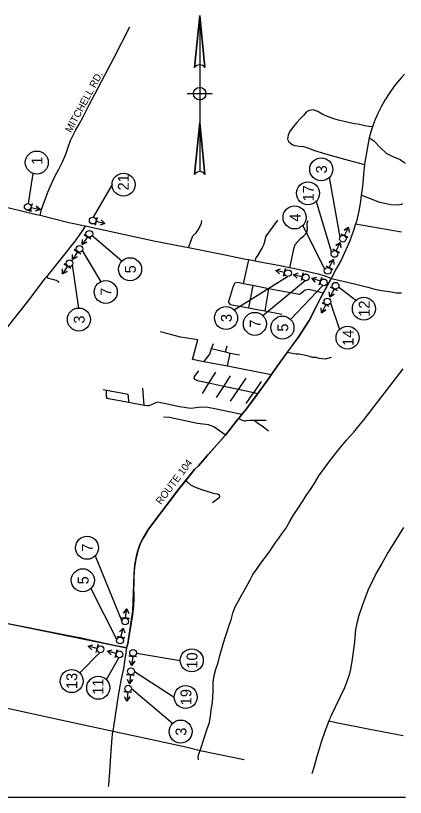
# Model space of a CAD drawing. Extents: x 1123038 to 1172987, y 554419 to 623636.
# Drawn here: x 1134979 to 1140976, y 566570 to 578600 of the extents above; entities that cross this region are included whole.
import ezdxf

# ---------------------------------------------------------------- set-up
doc = ezdxf.new("R2010")
doc.units = 0
for name, color, linetype in [('ANNOTATION', 7, 'Continuous'), ('CENTERLINE', 7, 'Continuous'), ('D_Text_Standard', 7, 'Continuous'), ('Default', 7, 'Continuous'), ('H_V CONTROLS', 7, 'Continuous'), ('Maine_E911_Roads', 7, 'Continuous'), ('Metwp24L', 7, 'Continuous')]:
    doc.layers.add(name, color=color, linetype=linetype)

msp = doc.modelspace()

# ---------------------------------------------------------------- linework, layer by layer
at = {"layer": 'ANNOTATION'}
msp.add_line((1140976, 566570), (1123076, 566570), dxfattribs=at)
at = {"layer": 'CENTERLINE'}
for points in [[(1138845, 572976), (1139007, 573210), (1139242, 573535), (1139325, 573649), (1139494, 573909), (1139710, 574328), (1139836, 574557)], [(1136846, 570308), (1136859, 570363), (1136896, 570470), (1136941, 570559), (1137024, 570699), (1137481, 571305), (1137732, 571618), (1137792, 571673), (1137941, 571847), (1138206, 572143), (1138405, 572396), (1138421, 572409), (1138548, 572572), (1138845, 572976)], [(1130112, 570269), (1130133, 570251), (1130186, 570222), (1130224, 570205), (1130658, 570099), (1130944, 570047), (1136685, 568871)], [(1136685, 568871), (1136707, 568934), (1136784, 569437), (1136801, 570001), (1136813, 570149), (1136846, 570308)]]:
    msp.add_lwpolyline(points, dxfattribs=at)
at = {"layer": 'D_Text_Standard'}
for p, q in [((1135243, 576172), (1135174, 575709)), ((1136463, 576000), (1136174, 575497)), ((1139806, 576110), (1139966, 575190)), ((1139602, 575741), (1139837, 574956)), ((1139396, 575370), (1139733, 574697)), ((1136615, 574823), (1136157, 575214)), ((1136005, 574984), (1136290, 574502)), ((1135952, 574101), (1135852, 574763)), ((1138342, 574073), (1139161, 574586)), ((1139434, 574521), (1138785, 573982)), ((1139210, 573925), (1139705, 574446)), ((1140212, 574215), (1139949, 574421)), ((1139823, 574179), (1139961, 573769)), ((1136203, 570286), (1136612, 569282)), ((1136138, 569787), (1136535, 568996)), ((1135966, 568485), (1136274, 568798)), ((1136838, 568789), (1137512, 568679)), ((1136375, 568382), (1136568, 568720)), ((1137512, 568679), (1137512, 568679)), ((1136806, 568506), (1137418, 568114)), ((1137393, 567708), (1136762, 568240))]:
    msp.add_line(p, q, dxfattribs=at)
for centre in [(1135305, 576340), (1139681, 576235), (1136639, 576000), (1139477, 575866), (1139271, 575495), (1136740, 574698), (1136366, 574348), (1140337, 574090), (1135952, 573924), (1138217, 573948), (1138660, 573857), (1139085, 573800), (1140086, 573644), (1136078, 570411), (1136013, 569912), (1137689, 568679), (1135841, 568360), (1136250, 568257), (1137595, 568114), (1137518, 567583)]:
    msp.add_circle(centre, 177, dxfattribs=at)
at = {"layer": 'Default'}
for points in [[(1135231, 575707), (1135204, 575587), (1135218, 575647), (1135354, 575616), (1135295, 575670), (1135354, 575616), (1135282, 575590)], [(1136232, 575494), (1136205, 575375), (1136218, 575435), (1136354, 575404), (1136295, 575458), (1136354, 575404), (1136282, 575377)], [(1139984, 575245), (1140091, 575188), (1140038, 575217), (1140103, 575340), (1140036, 575297), (1140103, 575340), (1140110, 575263)], [(1136134, 575162), (1136033, 575230), (1136083, 575196), (1136005, 575080), (1136077, 575116), (1136005, 575080), (1136007, 575157)], [(1139855, 575010), (1139963, 574953), (1139909, 574982), (1139974, 575105), (1139907, 575062), (1139974, 575105), (1139981, 575028)], [(1135982, 574932), (1135881, 575000), (1135931, 574966), (1135853, 574850), (1135925, 574886), (1135853, 574850), (1135855, 574927)], [(1139750, 574751), (1139858, 574694), (1139804, 574723), (1139870, 574846), (1139802, 574803), (1139870, 574846), (1139876, 574769)], [(1135829, 574710), (1135728, 574779), (1135779, 574745), (1135700, 574629), (1135772, 574665), (1135700, 574629), (1135702, 574706)], [(1139103, 574589), (1139130, 574708), (1139117, 574648), (1138981, 574679), (1139040, 574625), (1138981, 574679), (1139053, 574706)], [(1139377, 574523), (1139404, 574643), (1139390, 574583), (1139254, 574614), (1139313, 574560), (1139254, 574614), (1139326, 574641)], [(1139648, 574456), (1139690, 574570), (1139669, 574513), (1139538, 574561), (1139590, 574500), (1139538, 574561), (1139613, 574578)], [(1139932, 574367), (1139824, 574424), (1139878, 574395), (1139812, 574272), (1139880, 574315), (1139812, 574272), (1139806, 574349)], [(1139806, 574124), (1139698, 574181), (1139752, 574152), (1139686, 574029), (1139754, 574072), (1139686, 574029), (1139679, 574106)], [(1136610, 569340), (1136731, 569323), (1136670, 569331), (1136689, 569470), (1136641, 569406), (1136689, 569470), (1136722, 569400)], [(1136539, 569053), (1136657, 569023), (1136598, 569038), (1136632, 569174), (1136577, 569116), (1136632, 569174), (1136657, 569101)], [(1136217, 568802), (1136247, 568921), (1136232, 568861), (1136096, 568896), (1136154, 568840), (1136096, 568896), (1136169, 568920)], [(1136510, 568724), (1136540, 568842), (1136525, 568783), (1136390, 568818), (1136448, 568762), (1136390, 568818), (1136463, 568842)], [(1136841, 568732), (1136720, 568746), (1136780, 568739), (1136764, 568600), (1136811, 568665), (1136764, 568600), (1136730, 568670)], [(1136809, 568448), (1136687, 568463), (1136748, 568456), (1136731, 568317), (1136779, 568382), (1136731, 568317), (1136698, 568386)], [(1136765, 568182), (1136644, 568197), (1136705, 568189), (1136688, 568051), (1136735, 568115), (1136688, 568051), (1136654, 568120)]]:
    msp.add_lwpolyline(points, dxfattribs=at)
for centre in [(1135165, 575658), (1136165, 575446), (1136113, 575241), (1140013, 575168), (1135961, 575011), (1139884, 574933), (1135808, 574790), (1139170, 574637), (1139780, 574674), (1139443, 574572), (1139720, 574495), (1139902, 574444), (1139776, 574201), (1136664, 569278), (1136585, 568986), (1136284, 568849), (1136578, 568771), (1136786, 568793), (1136754, 568510), (1136710, 568243)]:
    msp.add_circle(centre, 51.9, dxfattribs=at)
at = {"layer": 'H_V CONTROLS'}
for p, q in [((1137732, 577800), (1137812, 578600)), ((1137812, 578600), (1137812, 576200)), ((1137812, 578600), (1137892, 577800)), ((1137620, 577400), (1138004, 577400)), ((1137732, 576157), (1137812, 576957)), ((1137812, 576957), (1137892, 576157))]:
    msp.add_line(p, q, dxfattribs=at)
for points in [[(1137892, 577800), (1137812, 578600), (1137772, 578200), (1137732, 577800)], [(1137892, 576157), (1137812, 576957), (1137772, 576557), (1137732, 576157)]]:
    msp.add_lwpolyline(points, dxfattribs=at)
msp.add_circle((1137812, 577400), 96, dxfattribs=at)
for centre in [(1137812, 577747), (1137812, 577747), (1137812, 576104), (1137812, 576104)]:
    msp.add_arc(centre, 96, 33.5573, 146.4427, dxfattribs=at)
at = {"layer": 'Maine_E911_Roads'}
for points in [[(1135357, 575524), (1135379, 575618), (1135474, 575882), (1135531, 576011), (1135583, 576127), (1135642, 576239), (1135706, 576359), (1135750, 576468), (1135786, 576577), (1135822, 576681), (1135901, 576831), (1135954, 576929), (1136011, 577033), (1136105, 577215), (1136255, 577502), (1136496, 577957), (1136736, 578426)], [(1140961, 577699), (1140909, 577641), (1140806, 577514), (1140725, 577403), (1140661, 577302), (1140604, 577196), (1140560, 577105), (1140512, 577002), (1140482, 576918), (1140468, 576887)], [(1140468, 576887), (1140416, 576892), (1140353, 576903), (1140269, 576924), (1140192, 576936), (1140121, 576953), (1140057, 576968), (1139946, 576991), (1139874, 577011), (1139778, 577047), (1139697, 577085), (1139627, 577125), (1139555, 577150), (1139497, 577141), (1139447, 577116), (1139407, 577061), (1139358, 577011), (1139302, 576951), (1139233, 576868), (1139194, 576810), (1139172, 576762), (1139160, 576701), (1139182, 576660), (1139209, 576637), (1139244, 576613), (1139273, 576601), (1139342, 576594), (1139410, 576587), (1139476, 576566), (1139562, 576532), (1139745, 576476), (1140037, 576390), (1140348, 576307)], [(1140468, 576887), (1140445, 576813), (1140420, 576722)], [(1140420, 576722), (1140359, 576376), (1140348, 576307)], [(1140420, 576722), (1140485, 576679), (1140592, 576566), (1140679, 576482), (1140783, 576432), (1140894, 576387), (1140952, 576347), (1140971, 576327)], [(1135357, 575524), (1135278, 575539), (1134683, 575685), (1133226, 575982), (1132575, 576122), (1132376, 576166), (1131980, 576258), (1131516, 576373), (1131252, 576438)], [(1140348, 576307), (1140334, 576164), (1140319, 576019), (1140304, 575898), (1140297, 575842), (1140297, 575837)], [(1140297, 575837), (1140286, 575746), (1140266, 575618), (1140222, 575432), (1140211, 575397)], [(1140930, 575706), (1140917, 575693), (1140886, 575687), (1140843, 575685), (1140754, 575690), (1140585, 575727), (1140297, 575837)], [(1135230, 575587), (1135151, 575606)], [(1136048, 575360), (1135796, 575411), (1135357, 575524)], [(1137637, 575025), (1137648, 575057), (1137706, 575212), (1137758, 575259), (1137792, 575309), (1137838, 575406), (1137843, 575447)], [(1138663, 574823), (1138674, 574861), (1138714, 574927), (1138775, 575023), (1138798, 575075), (1138820, 575144), (1138831, 575197), (1138848, 575228), (1139012, 575454)], [(1139200, 574719), (1139238, 574911), (1139259, 575013), (1139282, 575078), (1139360, 575173), (1139408, 575206), (1139462, 575261), (1139471, 575311), (1139463, 575375), (1139464, 575409), (1139478, 575447)], [(1140211, 575397), (1140175, 575278), (1140120, 575135), (1140060, 574997), (1139986, 574839), (1139903, 574686), (1139854, 574590), (1139836, 574557)], [(1140211, 575397), (1140914, 575273)], [(1136048, 575360), (1135993, 575272), (1135896, 575134), (1135452, 574583)], [(1137637, 575025), (1137555, 575042), (1137107, 575130), (1136048, 575360)], [(1138561, 574842), (1138521, 574850), (1138151, 574923), (1137637, 575025)], [(1138561, 574842), (1138480, 574475)], [(1138663, 574823), (1138643, 574826), (1138561, 574842)], [(1139200, 574719), (1139052, 574749), (1138742, 574809), (1138663, 574823)], [(1139836, 574557), (1139727, 574596), (1139653, 574615), (1139320, 574694), (1139200, 574719)], [(1135452, 574583), (1135423, 574548), (1135180, 574229), (1134927, 573903), (1134650, 573556), (1134620, 573517), (1134244, 573043), (1134002, 572749), (1133422, 572023), (1132636, 571025), (1131932, 570140), (1131751, 569881)], [(1135452, 574583), (1135487, 574559), (1135521, 574548), (1135568, 574538), (1135579, 574535), (1135602, 574527), (1135610, 574524), (1135624, 574517), (1135634, 574511), (1135645, 574496)], [(1139836, 574557), (1139710, 574328)], [(1139836, 574557), (1139999, 574519), (1140213, 574468), (1140400, 574422), (1140505, 574393), (1140611, 574370), (1140648, 574367), (1140727, 574354), (1140841, 574333), (1140917, 574337)], [(1138480, 574475), (1138396, 574492), (1138354, 574484), (1138325, 574435), (1138266, 574233), (1138255, 574199), (1138252, 574184), (1138280, 574157), (1138560, 574106)], [(1138628, 574446), (1138480, 574475)], [(1138628, 574446), (1138560, 574106)], [(1138872, 574396), (1138628, 574446)], [(1138872, 574396), (1138812, 574059)], [(1139710, 574328), (1139493, 574384), (1139434, 574378), (1139364, 574321), (1139345, 574309), (1138872, 574396)], [(1139710, 574328), (1139669, 574254), (1139494, 573909), (1139325, 573649), (1139159, 573421)], [(1138560, 574106), (1138812, 574059)], [(1138812, 574059), (1139074, 574007)], [(1137782, 573610), (1137518, 573650), (1137206, 573736)], [(1137877, 573273), (1137702, 573311), (1137782, 573610)], [(1137877, 573273), (1137965, 573393), (1137995, 573476)], [(1137995, 573476), (1138023, 573555)], [(1137995, 573476), (1138209, 573425)], [(1138209, 573425), (1138232, 573521)], [(1138209, 573425), (1138275, 573408), (1138280, 573408)], [(1138237, 573204), (1138280, 573408)], [(1138280, 573408), (1138426, 573379)], [(1139159, 573421), (1139153, 573413), (1139007, 573210), (1138911, 573071)], [(1139159, 573421), (1139209, 573409), (1139294, 573396), (1139335, 573395), (1139418, 573383), (1139482, 573364), (1139541, 573347), (1139596, 573342), (1139645, 573329), (1139747, 573321), (1139840, 573346)], [(1138237, 573204), (1137877, 573273)], [(1137951, 572943), (1137778, 572980), (1137742, 573002), (1137727, 573021), (1137731, 573048), (1137799, 573134)], [(1137951, 572943), (1138060, 573114)], [(1138911, 573071), (1138237, 573204)], [(1138185, 572893), (1138284, 573059)], [(1138409, 572847), (1138528, 573020)], [(1138911, 573071), (1138885, 573034), (1138805, 572918), (1138720, 572805), (1138701, 572780)], [(1136956, 572601), (1136937, 572865)], [(1137852, 572785), (1137951, 572943)], [(1138185, 572893), (1137951, 572943)], [(1138070, 572722), (1138185, 572893)], [(1138409, 572847), (1138185, 572893)], [(1138643, 572797), (1138763, 572972)], [(1136377, 572831), (1136325, 572842)], [(1136720, 572645), (1136714, 572753), (1136703, 572771), (1136684, 572774), (1136377, 572831)], [(1136720, 572645), (1136409, 572702), (1136391, 572708), (1136377, 572733), (1136377, 572831)], [(1138287, 572668), (1138409, 572847)], [(1138643, 572797), (1138409, 572847)], [(1138701, 572780), (1138693, 572768), (1138548, 572572), (1138462, 572463)], [(1138526, 572634), (1138627, 572780), (1138643, 572797)], [(1138701, 572780), (1138643, 572797)], [(1136956, 572601), (1136720, 572645)], [(1138462, 572463), (1138043, 572547), (1137939, 572570), (1137836, 572577), (1137675, 572553), (1137499, 572579), (1137265, 572631), (1137180, 572649), (1137160, 572651), (1137134, 572644), (1137030, 572598), (1137002, 572596), (1136956, 572601)], [(1138206, 572143), (1138081, 572238), (1138030, 572273), (1137949, 572303), (1137779, 572325), (1137348, 572414), (1137254, 572423)], [(1138413, 572403), (1138405, 572396), (1138206, 572143)], [(1138462, 572463), (1138421, 572409), (1138413, 572403)], [(1138413, 572403), (1138463, 572374), (1138478, 572369), (1138493, 572366), (1138509, 572367), (1138524, 572368), (1138584, 572373), (1138617, 572375), (1138648, 572374)], [(1138648, 572374), (1138836, 572375)], [(1138648, 572374), (1138673, 572355), (1138722, 572319), (1138770, 572286), (1138821, 572250), (1138871, 572213)], [(1138206, 572143), (1138195, 572130), (1137919, 571823), (1137792, 571673), (1137732, 571618), (1137653, 571518), (1137596, 571445)], [(1137596, 571445), (1137481, 571305), (1137376, 571162), (1137228, 570971), (1137024, 570699), (1136941, 570559), (1136896, 570470), (1136859, 570363), (1136833, 570254), (1136813, 570149), (1136803, 570056), (1136799, 569946), (1136797, 569858), (1136795, 569771), (1136796, 569708), (1136796, 569620), (1136791, 569516), (1136777, 569380), (1136749, 569189), (1136728, 569070), (1136707, 568934), (1136685, 568871)], [(1137596, 571445), (1137669, 571382), (1137722, 571352), (1137783, 571329), (1137852, 571303), (1137970, 571268), (1138040, 571249), (1138085, 571242), (1138111, 571224), (1138118, 571203), (1138111, 571178), (1138089, 571163), (1138010, 571103)], [(1140948, 570724), (1140881, 570617), (1140713, 570342), (1140614, 570168), (1140526, 570022), (1140398, 569754), (1140346, 569617), (1140316, 569531), (1140262, 569369), (1140232, 569274), (1140211, 569154), (1140205, 569096), (1140191, 568960), (1140152, 568659), (1140131, 568545), (1140109, 568458), (1140070, 568336), (1140039, 568258), (1139969, 568109), (1139896, 567957), (1139839, 567838), (1139820, 567798), (1139814, 567781), (1139800, 567747)], [(1136685, 568871), (1136422, 568922), (1135987, 569019), (1135748, 569065), (1135253, 569164), (1134467, 569320), (1132687, 569692), (1131888, 569851)], [(1136685, 568871), (1136637, 568552), (1136600, 568367), (1136558, 568137), (1136490, 567694), (1136477, 567589)], [(1139800, 567747), (1139732, 567570), (1139684, 567436), (1139614, 567200), (1139569, 567031), (1139536, 566935)], [(1139800, 567747), (1139913, 567721), (1140406, 567627), (1140941, 567521)], [(1136408, 566736), (1136411, 566759), (1136432, 567037), (1136443, 567209), (1136464, 567487), (1136477, 567589)]]:
    msp.add_lwpolyline(points, dxfattribs=at)
at = {"layer": 'Metwp24L'}
for points in [[(1137816, 567290), (1137884, 567495), (1137919, 567612), (1137960, 567724), (1137977, 567818), (1137988, 567916), (1138007, 568030), (1138018, 568204), (1138020, 568342), (1138033, 568447), (1138061, 568541), (1138096, 568647), (1138123, 568754), (1138179, 568950), (1138208, 569044), (1138239, 569137), (1138265, 569219), (1138294, 569304), (1138321, 569407), (1138356, 569503), (1138460, 569687), (1138527, 569805), (1138586, 569919), (1138630, 570000), (1138685, 570075), (1138754, 570176), (1138894, 570366), (1138942, 570437), (1138983, 570499), (1139027, 570560), (1139076, 570625), (1139139, 570710), (1139187, 570801), (1139259, 570925), (1139325, 571020), (1139402, 571137), (1139451, 571217), (1139514, 571307), (1139571, 571393), (1139642, 571516), (1139814, 571750), (1139970, 571945), (1140071, 572068), (1140182, 572190), (1140259, 572288), (1140344, 572384), (1140943, 573166)], [(1126495, 569760), (1126565, 569745), (1128542, 569315), (1130793, 568831), (1132522, 568448), (1134165, 568093), (1135956, 567702), (1137599, 567347), (1137816, 567290)], [(1137791, 567150), (1137786, 567206), (1137802, 567252), (1137816, 567290)], [(1137816, 567290), (1138497, 567155)]]:
    msp.add_lwpolyline(points, dxfattribs=at)

# ---------------------------------------------------------------- texts
at = {"layer": 'D_Text_Standard'}
for s, height, rotation, p in [('MITCHELL RD.', 111.99, 61.5891, (1135832, 576790)), ('1', 167, 90, (1135391, 576307)), ('3', 167, 90, (1139769, 576172)), ('21', 167.1, 90, (1136720, 575910)), ('17', 167.1, 90, (1139566, 575742)), ('4', 167, 90, (1139363, 575431)), ('5', 167, 90, (1136828, 574635)), ('7', 167, 90, (1136454, 574288)), ('12', 167.1, 90, (1140427, 573967)), ('3', 167, 90, (1136041, 573861)), ('3', 167, 90, (1138305, 573885)), ('7', 167, 90, (1138748, 573797)), ('5', 167, 90, (1139173, 573737)), ('14', 167.1, 90, (1140178, 573519)), ('ROUTE 104', 112, 53.0255, (1137215, 571067)), ('7', 167, 90, (1136166, 570351)), ('5', 167, 90, (1136102, 569849)), ('10', 167.1, 90, (1137777, 568552)), ('13', 167.1, 90, (1135927, 568238)), ('11', 167.1, 90, (1136329, 568150)), ('19', 167.1, 90, (1137683, 567988)), ('3', 167, 90, (1137607, 567520))]:
    msp.add_text(s, height=height, rotation=rotation, dxfattribs=at).set_placement(p)

doc.saveas('drawing.dxf')
